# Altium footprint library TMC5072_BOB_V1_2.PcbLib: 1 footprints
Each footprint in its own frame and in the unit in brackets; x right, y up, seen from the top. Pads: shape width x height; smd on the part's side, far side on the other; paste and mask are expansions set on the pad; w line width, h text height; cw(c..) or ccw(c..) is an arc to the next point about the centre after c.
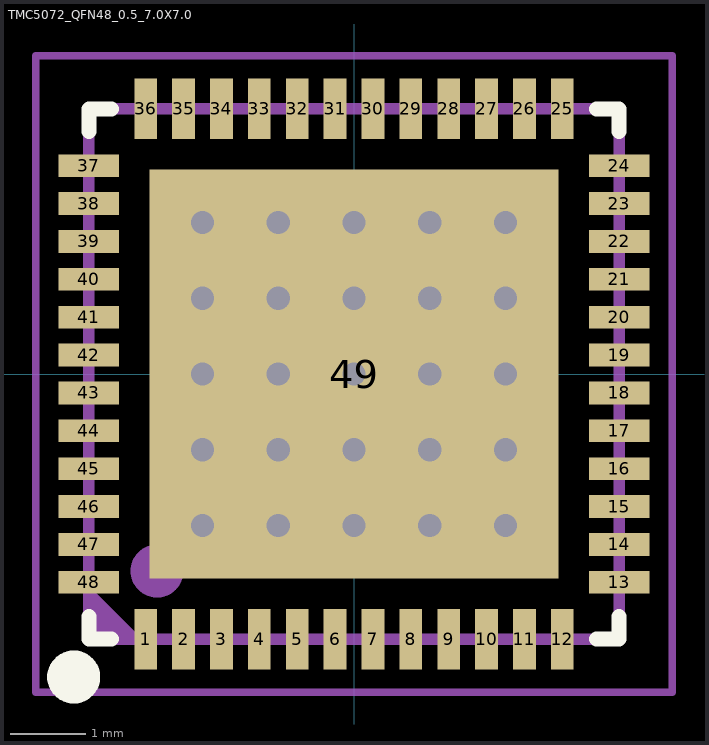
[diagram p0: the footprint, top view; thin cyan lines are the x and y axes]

## TMC5072_QFN48_0.5_7.0X7.0 [mm]
pads (49):
  rect 0.3x0.8 smd: 1(-2.75,-3.5) 2(-2.25,-3.5) 3(-1.75,-3.5) 4(-1.25,-3.5) 5(-0.75,-3.5) 6(-0.25,-3.5) 7(0.25,-3.5) 8(0.75,-3.5) 9(1.25,-3.5) 10(1.75,-3.5) 11(2.25,-3.5) 12(2.75,-3.5) 25(2.75,3.5) 26(2.25,3.5) 27(1.75,3.5) 28(1.25,3.5) 29(0.75,3.5) 30(0.25,3.5) 31(-0.25,3.5) 32(-0.75,3.5) 33(-1.25,3.5) 34(-1.75,3.5) 35(-2.25,3.5) 36(-2.75,3.5)
  rect 0.8x0.3 smd: 13(3.5,-2.75) 14(3.5,-2.25) 15(3.5,-1.75) 16(3.5,-1.25) 17(3.5,-0.75) 18(3.5,-0.25) 19(3.5,0.25) 20(3.5,0.75) 21(3.5,1.25) 22(3.5,1.75) 23(3.5,2.25) 24(3.5,2.75) 37(-3.5,2.75) 38(-3.5,2.25) 39(-3.5,1.75) 40(-3.5,1.25) 41(-3.5,0.75) 42(-3.5,0.25) 43(-3.5,-0.25) 44(-3.5,-0.75) 45(-3.5,-1.25) 46(-3.5,-1.75) 47(-3.5,-2.25) 48(-3.5,-2.75)
  rect 5.4x5.4 smd paste-25.4: 49(0,0)
via -2,-2 diameter 0.686 hole 0.305
via -1,-2 diameter 0.686 hole 0.305
via 0,-2 diameter 0.686 hole 0.305
via 1,-2 diameter 0.686 hole 0.305
via 2,-2 diameter 0.686 hole 0.305
via -2,-1 diameter 0.686 hole 0.305
via -1,-1 diameter 0.686 hole 0.305
via 0,-1 diameter 0.686 hole 0.305
via 1,-1 diameter 0.686 hole 0.305
via 2,-1 diameter 0.686 hole 0.305
via -2,0 diameter 0.686 hole 0.305
via -1,0 diameter 0.686 hole 0.305
via 0,0 diameter 0.686 hole 0.305
via 1,0 diameter 0.686 hole 0.305
via 2,0 diameter 0.686 hole 0.305
via -2,1 diameter 0.686 hole 0.305
via -1,1 diameter 0.686 hole 0.305
via 0,1 diameter 0.686 hole 0.305
via 1,1 diameter 0.686 hole 0.305
via 2,1 diameter 0.686 hole 0.305
via 2,2 diameter 0.686 hole 0.305
via 1,2 diameter 0.686 hole 0.305
via 0,2 diameter 0.686 hole 0.305
via -1,2 diameter 0.686 hole 0.305
via -2,2 diameter 0.686 hole 0.305
Top Overlay:
  circle w0.5: c-3.7,-4 r0.1
  lines w0.2: -3.5,-3.2 -3.5,-3.5 -3.2,-3.5 ; -3.5,3.2 -3.5,3.5 -3.2,3.5 ; 3.2,-3.5 3.5,-3.5 3.5,-3.2 ; 3.2,3.5 3.5,3.5 3.5,3.2
Top Paste:
  region: 0.3,-2.125 0.3,-0.3 2.125,-0.3 2.125,-2.125
  region: -2.125,-2.125 -2.125,-0.3 -0.3,-0.3 -0.3,-2.125
  region: 0.3,0.3 0.3,2.125 2.125,2.125 2.115,0.3
  region: -2.125,0.3 -2.125,2.125 -0.3,2.125 -0.3,0.3
Bottom Solder:
  region: -2.54,2.54 2.54,2.54 2.54,-2.54 -2.54,-2.54
Mechanical 13:
  circle w0.5: c-2.6,-2.6 r0.1
  lines w0.15: -3.5,-3.5 3.5,-3.5 3.5,3.5 -3.5,3.5 -3.5,-3.5
Mechanical 15:
  lines w0.1: -4.2,-4.2 4.2,-4.2 4.2,4.2 -4.2,4.2 -4.2,-4.2
TopAsm:
  circle w0.5: c-2.6,-2.6 r0.1
  region: -3.5,-2.794 -2.794,-3.5 -3.5,-3.5
  lines w0.076: -3.5,-3.5 -3.5,3.5 3.5,3.5 3.5,-3.5 -3.5,-3.5
  text ".Designator" at -2.6,-0.7 h1.27
3D body: height 0.9, standoff 0, extent -3.5,-3.5 3.5,3.5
